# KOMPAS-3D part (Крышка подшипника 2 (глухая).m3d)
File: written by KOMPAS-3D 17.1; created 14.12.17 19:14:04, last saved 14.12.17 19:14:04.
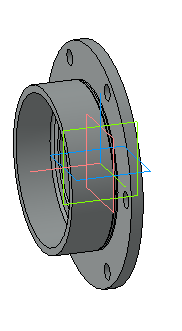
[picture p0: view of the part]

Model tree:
1. Операция без истории:1  (labels: Крышка подшипника 2 (глухая))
